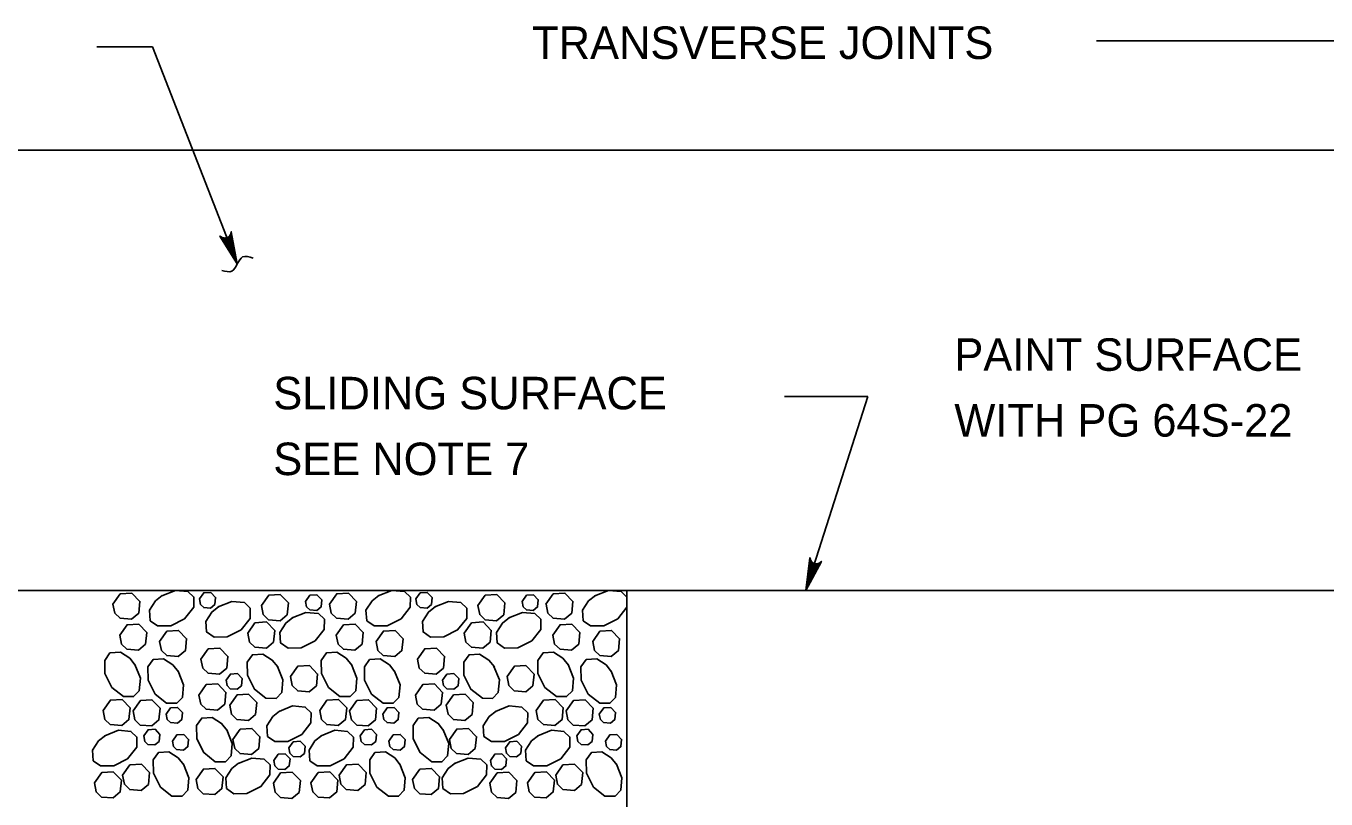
# Model space of a CAD drawing. Extents: x 2084213 to 2099800, y 976677 to 981262.
# Drawn here: x 2094470.4 to 2094864.1, y 979143.5 to 979377.6 of the extents above; entities that cross this region are included whole.
import ezdxf

# ---------------------------------------------------------------- set-up
doc = ezdxf.new("R2010")
doc.units = 0
doc.layers.add('1', color=7, linetype='Continuous')

msp = doc.modelspace()

# ---------------------------------------------------------------- linework, layer by layer
at = {"layer": '1'}
for p, q in [((2094794.55, 979373.09), (2094946.76, 979373.09)), ((2094491.78, 979371.3), (2094508.67, 979371.3)), ((2094534.37, 979305.49), (2094508.67, 979371.3)), ((2094435.37, 979339.99), (2094902.37, 979339.99)), ((2094725.36, 979265.4), (2094700.05, 979265.4)), ((2094706.55, 979206.66), (2094725.36, 979265.4)), ((2094435.37, 979206.66), (2094902.37, 979206.66)), ((2094652.37, 979206.66), (2094652.37, 979106.66)), ((2094652.37, 979206.66), (2095252.37, 979206.66))]:
    msp.add_line(p, q, dxfattribs=at)
for points in [[(2094534.37, 979305.49), (2094529.1, 979313.94), (2094529.48, 979313.68), (2094529.86, 979313.43), (2094530.24, 979313.37), (2094530.61, 979313.3), (2094530.94, 979313.37), (2094531.27, 979313.44), (2094531.55, 979313.61), (2094531.84, 979313.78), (2094532.07, 979314.08), (2094532.31, 979314.38), (2094532.41, 979314.83), (2094532.52, 979315.27), (2094534.37, 979305.49), (2094532.41, 979314.83), (2094532.31, 979314.38), (2094534.37, 979305.49), (2094532.07, 979314.08), (2094531.84, 979313.78), (2094534.37, 979305.49), (2094531.55, 979313.61), (2094531.27, 979313.44), (2094534.37, 979305.49), (2094530.94, 979313.37), (2094530.61, 979313.3), (2094534.37, 979305.49), (2094530.24, 979313.37), (2094529.86, 979313.43), (2094534.37, 979305.49), (2094529.48, 979313.68)], [(2094706.55, 979206.66), (2094711.28, 979215.42), (2094710.92, 979215.14), (2094710.56, 979214.86), (2094710.19, 979214.77), (2094709.81, 979214.69), (2094709.48, 979214.74), (2094709.15, 979214.78), (2094708.86, 979214.94), (2094708.56, 979215.09), (2094708.31, 979215.37), (2094708.06, 979215.66), (2094707.92, 979216.1), (2094707.79, 979216.54), (2094706.55, 979206.66), (2094707.92, 979216.1), (2094708.06, 979215.66), (2094706.55, 979206.66), (2094708.31, 979215.37), (2094708.56, 979215.09), (2094706.55, 979206.66), (2094708.86, 979214.94), (2094709.15, 979214.78), (2094706.55, 979206.66), (2094709.48, 979214.74), (2094709.81, 979214.69), (2094706.55, 979206.66), (2094710.19, 979214.77), (2094710.56, 979214.86), (2094706.55, 979206.66), (2094710.92, 979215.14)], [(2094515.62, 979206.66), (2094519.41, 979206.33), (2094521.21, 979204.62), (2094521.16, 979201.54), (2094518.42, 979198.05), (2094514.2, 979195.93), (2094510.21, 979195.87), (2094507.97, 979197.46), (2094507.76, 979200.63), (2094509.58, 979203.47), (2094511.66, 979205.13)], [(2094511.5, 979205.02), (2094515.62, 979206.66)], [(2094581.2, 979206.66), (2094584.99, 979206.33), (2094586.79, 979204.62), (2094586.74, 979201.54), (2094584, 979198.05), (2094579.78, 979195.93), (2094575.79, 979195.87), (2094573.55, 979197.46), (2094573.34, 979200.63), (2094575.16, 979203.47), (2094577.24, 979205.13)], [(2094577.07, 979205.02), (2094581.2, 979206.66)], [(2094642.65, 979205.02), (2094646.78, 979206.66)], [(2094646.78, 979206.66), (2094650.57, 979206.33), (2094652.37, 979204.62)], [(2094496.7, 979202.51), (2094498.9, 979205.65), (2094502.42, 979205.85), (2094504.87, 979203.32), (2094504.52, 979199.76), (2094502.34, 979197.95), (2094498.86, 979198.2), (2094497.23, 979199.79), (2094496.7, 979202.51)], [(2094522.88, 979204.05), (2094524.2, 979205.93), (2094526.32, 979206.05), (2094527.78, 979204.53), (2094527.57, 979202.4), (2094526.27, 979201.31), (2094524.18, 979201.46), (2094523.2, 979202.42), (2094522.88, 979204.05)], [(2094528.6, 979201.64), (2094532.72, 979203.27), (2094536.51, 979202.94), (2094538.31, 979201.23), (2094538.26, 979198.16), (2094535.52, 979194.66), (2094531.3, 979192.55), (2094527.31, 979192.48), (2094525.07, 979194.07), (2094524.86, 979197.24), (2094526.68, 979200.08), (2094528.76, 979201.74)], [(2094541.66, 979202.04), (2094543.87, 979205.18), (2094547.39, 979205.38), (2094549.84, 979202.84), (2094549.48, 979199.28), (2094547.31, 979197.47), (2094543.83, 979197.72), (2094542.2, 979199.31), (2094541.66, 979202.04)], [(2094555.05, 979203.33), (2094556.37, 979205.21), (2094558.48, 979205.33), (2094559.95, 979203.81), (2094559.74, 979201.67), (2094558.43, 979200.59), (2094556.35, 979200.74), (2094555.37, 979201.69), (2094555.05, 979203.33)], [(2094562.27, 979202.51), (2094564.48, 979205.65), (2094568, 979205.85), (2094570.45, 979203.32), (2094570.09, 979199.76), (2094567.92, 979197.95), (2094564.44, 979198.2), (2094562.81, 979199.79), (2094562.28, 979202.51)], [(2094588.46, 979204.05), (2094589.78, 979205.93), (2094591.9, 979206.05), (2094593.36, 979204.53), (2094593.15, 979202.4), (2094591.85, 979201.31), (2094589.76, 979201.46), (2094588.78, 979202.42), (2094588.46, 979204.05)], [(2094594.17, 979201.64), (2094598.3, 979203.27), (2094602.09, 979202.94), (2094603.89, 979201.23), (2094603.83, 979198.16), (2094601.1, 979194.66), (2094596.88, 979192.55), (2094592.89, 979192.48), (2094590.65, 979194.07), (2094590.44, 979197.24), (2094592.26, 979200.08), (2094594.34, 979201.74)], [(2094607.24, 979202.04), (2094609.45, 979205.18), (2094612.97, 979205.38), (2094615.42, 979202.84), (2094615.06, 979199.28), (2094612.89, 979197.47), (2094609.41, 979197.72), (2094607.77, 979199.31), (2094607.24, 979202.04)], [(2094620.62, 979203.33), (2094621.95, 979205.21), (2094624.06, 979205.33), (2094625.53, 979203.81), (2094625.32, 979201.67), (2094624.01, 979200.59), (2094621.93, 979200.74), (2094620.94, 979201.69), (2094620.63, 979203.33)], [(2094627.85, 979202.51), (2094630.06, 979205.65), (2094633.58, 979205.85), (2094636.03, 979203.32), (2094635.67, 979199.76), (2094633.5, 979197.95), (2094630.02, 979198.2), (2094628.39, 979199.79), (2094627.86, 979202.51)], [(2094652.37, 979204.62), (2094652.32, 979201.54), (2094649.58, 979198.05), (2094645.36, 979195.93), (2094641.37, 979195.87), (2094639.13, 979197.46), (2094638.92, 979200.63), (2094640.74, 979203.47), (2094642.82, 979205.13)], [(2094551.01, 979198.3), (2094555.14, 979199.94), (2094558.93, 979199.61), (2094560.73, 979197.9), (2094560.67, 979194.82), (2094557.94, 979191.33), (2094553.71, 979189.21), (2094549.73, 979189.14), (2094547.49, 979190.73), (2094547.28, 979193.91), (2094549.1, 979196.74), (2094551.18, 979198.41)], [(2094616.59, 979198.3), (2094620.72, 979199.94), (2094624.51, 979199.61), (2094626.31, 979197.9), (2094626.25, 979194.82), (2094623.52, 979191.33), (2094619.29, 979189.21), (2094615.31, 979189.14), (2094613.07, 979190.73), (2094612.86, 979193.91), (2094614.67, 979196.74), (2094616.76, 979198.41)], [(2094498.77, 979193.12), (2094500.98, 979196.26), (2094504.5, 979196.46), (2094506.94, 979193.92), (2094506.59, 979190.37), (2094504.42, 979188.56), (2094500.94, 979188.81), (2094499.3, 979190.39), (2094498.77, 979193.12)], [(2094537.51, 979193.74), (2094539.72, 979196.87), (2094543.24, 979197.08), (2094545.69, 979194.54), (2094545.33, 979190.98), (2094543.16, 979189.17), (2094539.68, 979189.42), (2094538.05, 979191.01), (2094537.51, 979193.74)], [(2094564.35, 979193.12), (2094566.55, 979196.26), (2094570.08, 979196.46), (2094572.52, 979193.92), (2094572.17, 979190.37), (2094569.99, 979188.56), (2094566.52, 979188.81), (2094564.88, 979190.39), (2094564.35, 979193.12)], [(2094603.09, 979193.74), (2094605.3, 979196.87), (2094608.82, 979197.08), (2094611.27, 979194.54), (2094610.91, 979190.98), (2094608.74, 979189.17), (2094605.26, 979189.42), (2094603.62, 979191.01), (2094603.09, 979193.74)], [(2094629.93, 979193.12), (2094632.13, 979196.26), (2094635.66, 979196.46), (2094638.1, 979193.92), (2094637.75, 979190.37), (2094635.57, 979188.56), (2094632.1, 979188.81), (2094630.46, 979190.39), (2094629.93, 979193.12)], [(2094510.83, 979191.2), (2094513.03, 979194.34), (2094516.56, 979194.54), (2094519, 979192), (2094518.65, 979188.44), (2094516.47, 979186.63), (2094513, 979186.89), (2094511.36, 979188.47), (2094510.83, 979191.2)], [(2094576.41, 979191.2), (2094578.61, 979194.34), (2094582.14, 979194.54), (2094584.58, 979192), (2094584.23, 979188.44), (2094582.05, 979186.63), (2094578.58, 979186.89), (2094576.94, 979188.47), (2094576.41, 979191.2)], [(2094641.99, 979191.2), (2094644.19, 979194.34), (2094647.71, 979194.54), (2094650.16, 979192), (2094649.81, 979188.44), (2094647.63, 979186.63), (2094644.16, 979186.89), (2094642.52, 979188.47), (2094641.99, 979191.2)], [(2094503.36, 979184.18), (2094505, 979180.06), (2094504.67, 979176.27), (2094502.96, 979174.47), (2094499.88, 979174.52), (2094496.39, 979177.26), (2094494.27, 979181.48), (2094494.2, 979185.46), (2094495.79, 979187.71), (2094498.97, 979187.92), (2094501.8, 979186.1), (2094503.47, 979184.02)], [(2094523.37, 979185.86), (2094525.58, 979189), (2094529.1, 979189.2), (2094531.54, 979186.66), (2094531.19, 979183.11), (2094529.01, 979181.3), (2094525.54, 979181.55), (2094523.9, 979183.14), (2094523.37, 979185.86)], [(2094546.52, 979183.65), (2094548.16, 979179.52), (2094547.83, 979175.73), (2094546.12, 979173.93), (2094543.04, 979173.99), (2094539.55, 979176.72), (2094537.44, 979180.95), (2094537.36, 979184.93), (2094538.96, 979187.17), (2094542.13, 979187.38), (2094544.97, 979185.57), (2094546.63, 979183.48)], [(2094568.94, 979184.18), (2094570.58, 979180.06), (2094570.25, 979176.27), (2094568.53, 979174.47), (2094565.46, 979174.52), (2094561.96, 979177.26), (2094559.85, 979181.48), (2094559.78, 979185.46), (2094561.37, 979187.71), (2094564.55, 979187.92), (2094567.38, 979186.1), (2094569.04, 979184.02)], [(2094588.95, 979185.86), (2094591.15, 979189), (2094594.67, 979189.2), (2094597.12, 979186.66), (2094596.77, 979183.11), (2094594.59, 979181.3), (2094591.12, 979181.55), (2094589.48, 979183.14), (2094588.95, 979185.86)], [(2094612.1, 979183.65), (2094613.74, 979179.52), (2094613.41, 979175.73), (2094611.7, 979173.93), (2094608.62, 979173.99), (2094605.13, 979176.72), (2094603.01, 979180.95), (2094602.94, 979184.93), (2094604.54, 979187.17), (2094607.71, 979187.38), (2094610.55, 979185.57), (2094612.21, 979183.48)], [(2094634.52, 979184.18), (2094636.15, 979180.06), (2094635.83, 979176.27), (2094634.11, 979174.47), (2094631.04, 979174.52), (2094627.54, 979177.26), (2094625.43, 979181.48), (2094625.36, 979185.46), (2094626.95, 979187.71), (2094630.13, 979187.92), (2094632.96, 979186.1), (2094634.62, 979184.02)], [(2094516.44, 979182.18), (2094518.07, 979178.06), (2094517.75, 979174.26), (2094516.03, 979172.46), (2094512.96, 979172.52), (2094509.46, 979175.26), (2094507.35, 979179.48), (2094507.28, 979183.46), (2094508.87, 979185.71), (2094512.04, 979185.92), (2094514.88, 979184.1), (2094516.54, 979182.02)], [(2094550.48, 979180.53), (2094552.69, 979183.67), (2094556.21, 979183.87), (2094558.66, 979181.33), (2094558.31, 979177.77), (2094556.13, 979175.96), (2094552.65, 979176.21), (2094551.02, 979177.8), (2094550.49, 979180.53)], [(2094582.02, 979182.18), (2094583.65, 979178.06), (2094583.32, 979174.26), (2094581.61, 979172.46), (2094578.54, 979172.52), (2094575.04, 979175.26), (2094572.93, 979179.48), (2094572.86, 979183.46), (2094574.45, 979185.71), (2094577.62, 979185.92), (2094580.46, 979184.1), (2094582.12, 979182.02)], [(2094616.06, 979180.53), (2094618.27, 979183.67), (2094621.79, 979183.87), (2094624.24, 979181.33), (2094623.89, 979177.77), (2094621.71, 979175.96), (2094618.23, 979176.21), (2094616.6, 979177.8), (2094616.07, 979180.53)], [(2094647.59, 979182.18), (2094649.23, 979178.06), (2094648.9, 979174.26), (2094647.19, 979172.46), (2094644.12, 979172.52), (2094640.62, 979175.26), (2094638.51, 979179.48), (2094638.44, 979183.46), (2094640.03, 979185.71), (2094643.2, 979185.92), (2094646.04, 979184.1), (2094647.7, 979182.02)], [(2094530.95, 979179.44), (2094532.27, 979181.32), (2094534.38, 979181.44), (2094535.85, 979179.92), (2094535.64, 979177.78), (2094534.33, 979176.7), (2094532.25, 979176.85), (2094531.27, 979177.8), (2094530.95, 979179.44)], [(2094596.53, 979179.44), (2094597.85, 979181.32), (2094599.96, 979181.44), (2094601.43, 979179.92), (2094601.22, 979177.78), (2094599.91, 979176.7), (2094597.83, 979176.85), (2094596.85, 979177.8), (2094596.53, 979179.44)], [(2094522.75, 979174.97), (2094524.96, 979178.11), (2094528.48, 979178.31), (2094530.93, 979175.77), (2094530.57, 979172.21), (2094528.4, 979170.4), (2094524.92, 979170.66), (2094523.28, 979172.24), (2094522.75, 979174.97)], [(2094532.07, 979171.86), (2094534.28, 979174.99), (2094537.8, 979175.19), (2094540.25, 979172.66), (2094539.89, 979169.1), (2094537.72, 979167.29), (2094534.24, 979167.54), (2094532.6, 979169.13), (2094532.07, 979171.85)], [(2094588.33, 979174.97), (2094590.54, 979178.11), (2094594.06, 979178.31), (2094596.51, 979175.77), (2094596.15, 979172.21), (2094593.98, 979170.4), (2094590.5, 979170.66), (2094588.86, 979172.24), (2094588.33, 979174.97)], [(2094597.65, 979171.86), (2094599.86, 979174.99), (2094603.38, 979175.19), (2094605.83, 979172.66), (2094605.47, 979169.1), (2094603.3, 979167.29), (2094599.82, 979167.54), (2094598.18, 979169.13), (2094597.65, 979171.85)], [(2094493.73, 979170.3), (2094495.94, 979173.44), (2094499.46, 979173.64), (2094501.91, 979171.1), (2094501.55, 979167.54), (2094499.38, 979165.73), (2094495.9, 979165.99), (2094494.27, 979167.57), (2094493.73, 979170.3)], [(2094502.81, 979170.17), (2094505.01, 979173.3), (2094508.53, 979173.51), (2094510.98, 979170.97), (2094510.63, 979167.41), (2094508.45, 979165.6), (2094504.97, 979165.85), (2094503.34, 979167.44), (2094502.81, 979170.17)], [(2094512.84, 979169.2), (2094514.16, 979171.08), (2094516.28, 979171.2), (2094517.75, 979169.68), (2094517.53, 979167.54), (2094516.23, 979166.46), (2094514.14, 979166.61), (2094513.16, 979167.56), (2094512.84, 979169.2)], [(2094547.01, 979170.01), (2094551.13, 979171.65), (2094554.93, 979171.32), (2094556.73, 979169.61), (2094556.67, 979166.53), (2094553.93, 979163.04), (2094549.71, 979160.92), (2094545.73, 979160.85), (2094543.49, 979162.45), (2094543.27, 979165.62), (2094545.09, 979168.46), (2094547.17, 979170.12)], [(2094559.31, 979170.3), (2094561.52, 979173.44), (2094565.04, 979173.64), (2094567.49, 979171.1), (2094567.13, 979167.54), (2094564.96, 979165.73), (2094561.48, 979165.99), (2094559.85, 979167.57), (2094559.31, 979170.3)], [(2094568.39, 979170.17), (2094570.59, 979173.3), (2094574.11, 979173.51), (2094576.56, 979170.97), (2094576.21, 979167.41), (2094574.03, 979165.6), (2094570.55, 979165.85), (2094568.92, 979167.44), (2094568.39, 979170.17)], [(2094578.42, 979169.2), (2094579.74, 979171.08), (2094581.86, 979171.2), (2094583.33, 979169.68), (2094583.11, 979167.54), (2094581.81, 979166.46), (2094579.72, 979166.61), (2094578.74, 979167.56), (2094578.42, 979169.2)], [(2094612.59, 979170.01), (2094616.71, 979171.65), (2094620.5, 979171.32), (2094622.31, 979169.61), (2094622.25, 979166.53), (2094619.51, 979163.04), (2094615.29, 979160.92), (2094611.31, 979160.85), (2094609.06, 979162.45), (2094608.85, 979165.62), (2094610.67, 979168.46), (2094612.75, 979170.12)], [(2094624.89, 979170.3), (2094627.1, 979173.44), (2094630.62, 979173.64), (2094633.07, 979171.1), (2094632.71, 979167.54), (2094630.54, 979165.73), (2094627.06, 979165.99), (2094625.42, 979167.57), (2094624.89, 979170.3)], [(2094633.96, 979170.17), (2094636.17, 979173.3), (2094639.69, 979173.51), (2094642.14, 979170.97), (2094641.79, 979167.41), (2094639.61, 979165.6), (2094636.13, 979165.85), (2094634.5, 979167.44), (2094633.97, 979170.17)], [(2094644, 979169.2), (2094645.32, 979171.08), (2094647.44, 979171.2), (2094648.91, 979169.68), (2094648.69, 979167.54), (2094647.39, 979166.46), (2094645.3, 979166.61), (2094644.32, 979167.56), (2094644, 979169.2)], [(2094531.18, 979164.44), (2094532.81, 979160.31), (2094532.49, 979156.52), (2094530.77, 979154.72), (2094527.7, 979154.78), (2094524.2, 979157.51), (2094522.09, 979161.73), (2094522.02, 979165.72), (2094523.61, 979167.96), (2094526.79, 979168.17), (2094529.62, 979166.35), (2094531.28, 979164.27)], [(2094596.76, 979164.44), (2094598.39, 979160.31), (2094598.07, 979156.52), (2094596.35, 979154.72), (2094593.28, 979154.78), (2094589.78, 979157.51), (2094587.67, 979161.73), (2094587.6, 979165.72), (2094589.19, 979167.96), (2094592.36, 979168.17), (2094595.2, 979166.35), (2094596.86, 979164.27)], [(2094494.23, 979162.64), (2094498.36, 979164.28), (2094502.15, 979163.95), (2094503.95, 979162.24), (2094503.89, 979159.16), (2094501.16, 979155.67), (2094496.93, 979153.55), (2094492.95, 979153.48), (2094490.71, 979155.08), (2094490.5, 979158.25), (2094492.31, 979161.09), (2094494.4, 979162.75)], [(2094506.01, 979162.58), (2094507.34, 979164.46), (2094509.45, 979164.58), (2094510.92, 979163.06), (2094510.71, 979160.92), (2094509.4, 979159.84), (2094507.32, 979159.99), (2094506.33, 979160.94), (2094506.02, 979162.58)], [(2094533.05, 979161.53), (2094535.26, 979164.67), (2094538.78, 979164.87), (2094541.23, 979162.33), (2094540.87, 979158.78), (2094538.7, 979156.97), (2094535.22, 979157.22), (2094533.59, 979158.8), (2094533.05, 979161.53)], [(2094559.81, 979162.64), (2094563.94, 979164.28), (2094567.73, 979163.95), (2094569.53, 979162.24), (2094569.47, 979159.16), (2094566.74, 979155.67), (2094562.51, 979153.55), (2094558.53, 979153.48), (2094556.29, 979155.08), (2094556.08, 979158.25), (2094557.89, 979161.09), (2094559.98, 979162.75)], [(2094571.59, 979162.58), (2094572.92, 979164.46), (2094575.03, 979164.58), (2094576.5, 979163.06), (2094576.29, 979160.92), (2094574.98, 979159.84), (2094572.89, 979159.99), (2094571.91, 979160.94), (2094571.6, 979162.58)], [(2094598.63, 979161.53), (2094600.84, 979164.67), (2094604.36, 979164.87), (2094606.81, 979162.33), (2094606.45, 979158.78), (2094604.28, 979156.97), (2094600.8, 979157.22), (2094599.16, 979158.8), (2094598.63, 979161.53)], [(2094625.39, 979162.64), (2094629.52, 979164.28), (2094633.3, 979163.95), (2094635.11, 979162.24), (2094635.05, 979159.16), (2094632.32, 979155.67), (2094628.09, 979153.55), (2094624.11, 979153.48), (2094621.87, 979155.08), (2094621.65, 979158.25), (2094623.47, 979161.09), (2094625.56, 979162.75)], [(2094637.17, 979162.58), (2094638.5, 979164.46), (2094640.61, 979164.58), (2094642.08, 979163.06), (2094641.87, 979160.92), (2094640.56, 979159.84), (2094638.47, 979159.99), (2094637.49, 979160.94), (2094637.17, 979162.58)], [(2094514.7, 979161.03), (2094516.03, 979162.91), (2094518.14, 979163.03), (2094519.61, 979161.51), (2094519.4, 979159.37), (2094518.09, 979158.29), (2094516, 979158.44), (2094515.02, 979159.39), (2094514.7, 979161.03)], [(2094549.98, 979158.96), (2094551.3, 979160.84), (2094553.41, 979160.96), (2094554.88, 979159.44), (2094554.67, 979157.3), (2094553.37, 979156.22), (2094551.28, 979156.37), (2094550.3, 979157.32), (2094549.98, 979158.96)], [(2094580.28, 979161.03), (2094581.61, 979162.91), (2094583.72, 979163.03), (2094585.19, 979161.51), (2094584.97, 979159.37), (2094583.67, 979158.29), (2094581.58, 979158.44), (2094580.6, 979159.39), (2094580.28, 979161.03)], [(2094615.56, 979158.96), (2094616.88, 979160.84), (2094618.99, 979160.96), (2094620.46, 979159.44), (2094620.25, 979157.3), (2094618.94, 979156.22), (2094616.86, 979156.37), (2094615.88, 979157.32), (2094615.56, 979158.96)], [(2094645.86, 979161.03), (2094647.18, 979162.91), (2094649.3, 979163.03), (2094650.77, 979161.51), (2094650.55, 979159.37), (2094649.25, 979158.29), (2094647.16, 979158.44), (2094646.18, 979159.39), (2094645.86, 979161.03)], [(2094518.04, 979154.03), (2094519.67, 979149.9), (2094519.34, 979146.11), (2094517.63, 979144.31), (2094514.56, 979144.37), (2094511.06, 979147.1), (2094508.95, 979151.33), (2094508.88, 979155.31), (2094510.47, 979157.55), (2094513.64, 979157.76), (2094516.48, 979155.94), (2094518.14, 979153.86)], [(2094534.59, 979154.24), (2094538.72, 979155.87), (2094542.51, 979155.54), (2094544.31, 979153.83), (2094544.25, 979150.76), (2094541.52, 979147.26), (2094537.3, 979145.15), (2094533.31, 979145.08), (2094531.07, 979146.67), (2094530.86, 979149.84), (2094532.68, 979152.68), (2094534.76, 979154.34)], [(2094545.43, 979155.13), (2094546.75, 979157.01), (2094548.86, 979157.13), (2094550.33, 979155.61), (2094550.12, 979153.48), (2094548.81, 979152.39), (2094546.73, 979152.54), (2094545.75, 979153.49), (2094545.43, 979155.13)], [(2094583.61, 979154.03), (2094585.25, 979149.9), (2094584.92, 979146.11), (2094583.21, 979144.31), (2094580.14, 979144.37), (2094576.64, 979147.1), (2094574.53, 979151.33), (2094574.46, 979155.31), (2094576.05, 979157.55), (2094579.22, 979157.76), (2094582.06, 979155.94), (2094583.72, 979153.86)], [(2094600.17, 979154.24), (2094604.3, 979155.87), (2094608.09, 979155.54), (2094609.89, 979153.83), (2094609.83, 979150.76), (2094607.1, 979147.26), (2094602.87, 979145.15), (2094598.89, 979145.08), (2094596.65, 979146.67), (2094596.44, 979149.84), (2094598.26, 979152.68), (2094600.34, 979154.34)], [(2094611.01, 979155.13), (2094612.33, 979157.01), (2094614.44, 979157.13), (2094615.91, 979155.61), (2094615.7, 979153.48), (2094614.39, 979152.39), (2094612.31, 979152.54), (2094611.33, 979153.49), (2094611.01, 979155.13)], [(2094649.19, 979154.03), (2094650.83, 979149.9), (2094650.5, 979146.11), (2094648.79, 979144.31), (2094645.71, 979144.37), (2094642.22, 979147.1), (2094640.11, 979151.33), (2094640.04, 979155.31), (2094641.63, 979157.55), (2094644.8, 979157.76), (2094647.64, 979155.94), (2094649.3, 979153.86)], [(2094491.08, 979148.37), (2094493.29, 979151.5), (2094496.81, 979151.7), (2094499.26, 979149.17), (2094498.9, 979145.61), (2094496.73, 979143.8), (2094493.25, 979144.05), (2094491.61, 979145.64), (2094491.08, 979148.36)], [(2094499.64, 979150.67), (2094501.84, 979153.8), (2094505.36, 979154.01), (2094507.81, 979151.47), (2094507.46, 979147.91), (2094505.28, 979146.1), (2094501.8, 979146.35), (2094500.17, 979147.94), (2094499.64, 979150.67)], [(2094521.87, 979149.4), (2094524.08, 979152.54), (2094527.6, 979152.74), (2094530.05, 979150.2), (2094529.7, 979146.64), (2094527.52, 979144.83), (2094524.04, 979145.09), (2094522.41, 979146.67), (2094521.88, 979149.4)], [(2094545.28, 979148.24), (2094547.49, 979151.37), (2094551.01, 979151.57), (2094553.46, 979149.04), (2094553.1, 979145.48), (2094550.93, 979143.67), (2094547.45, 979143.92), (2094545.81, 979145.51), (2094545.28, 979148.23)], [(2094556.66, 979148.37), (2094558.87, 979151.5), (2094562.39, 979151.7), (2094564.84, 979149.17), (2094564.48, 979145.61), (2094562.31, 979143.8), (2094558.83, 979144.05), (2094557.19, 979145.64), (2094556.66, 979148.36)], [(2094565.21, 979150.67), (2094567.42, 979153.8), (2094570.94, 979154.01), (2094573.39, 979151.47), (2094573.04, 979147.91), (2094570.86, 979146.1), (2094567.38, 979146.35), (2094565.75, 979147.94), (2094565.22, 979150.67)], [(2094587.45, 979149.4), (2094589.66, 979152.54), (2094593.18, 979152.74), (2094595.63, 979150.2), (2094595.27, 979146.64), (2094593.1, 979144.83), (2094589.62, 979145.09), (2094587.99, 979146.67), (2094587.46, 979149.4)], [(2094610.86, 979148.24), (2094613.07, 979151.37), (2094616.59, 979151.57), (2094619.03, 979149.04), (2094618.68, 979145.48), (2094616.51, 979143.67), (2094613.03, 979143.92), (2094611.39, 979145.51), (2094610.86, 979148.23)], [(2094622.24, 979148.37), (2094624.44, 979151.5), (2094627.97, 979151.7), (2094630.41, 979149.17), (2094630.06, 979145.61), (2094627.88, 979143.8), (2094624.41, 979144.05), (2094622.77, 979145.64), (2094622.24, 979148.36)], [(2094630.79, 979150.67), (2094633, 979153.8), (2094636.52, 979154.01), (2094638.97, 979151.47), (2094638.61, 979147.91), (2094636.44, 979146.1), (2094632.96, 979146.35), (2094631.33, 979147.94), (2094630.79, 979150.67)]]:
    msp.add_lwpolyline(points, dxfattribs=at)
msp.add_spline([(2094539.17, 979307.25), (2094535.98, 979307.63), (2094532.74, 979303.33), (2094529.64, 979303.57)], degree=3, dxfattribs=at)

# ---------------------------------------------------------------- texts
for s, height, p in [('TRANSVERSE JOINTS', 9.8425, (2094623.65, 979367.57)), ('PAINT SURFACE', 9.8425, (2094751.52, 979273.14)), ('SLIDING SURFACE', 9.8425, (2094545.26, 979261.48)), ('WITH PG 64S-22', 9.8425, (2094751.52, 979253.22)), ('SEE NOTE 7', 9.843, (2094545.26, 979241.56))]:
    msp.add_text(s, height=height, dxfattribs=at).set_placement(p)

doc.saveas('drawing.dxf')
